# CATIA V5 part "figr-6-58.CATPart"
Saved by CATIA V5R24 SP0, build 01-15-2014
Part number: Part1
Bounding box of the stored display mesh (mm): x -50.648 to 50.648, y -72.183 to 72.183, z -40 to 40
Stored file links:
  D:\KAVITA\CATIA V5-6R2014 Project_ Kavita\CATIA V5-6R2014_partfiles\Partfiles\c06_catia_v5-6r2014_prt\figr-6-58.CATPart
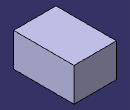
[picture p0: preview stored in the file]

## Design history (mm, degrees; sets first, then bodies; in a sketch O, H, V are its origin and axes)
Body1 (main body)
  Sketch1 on xy-plane, origin (0, 0, 0), H (1, 0, 0), V (0, 1, 0)
    line L1 (-50.6478, 72.1832) -> (50.6478, 72.1832)
    line L2 (50.6478, 72.1832) -> (50.6478, -72.1832)
    line L3 (50.6478, -72.1832) -> (-50.6478, -72.1832)
    line L4 (-50.6478, -72.1832) -> (-50.6478, 72.1832)
    axis line L5 (50.6478, -72.1832) -> (-50.6478, 72.1832)
    horizontal: L1 H, L3 H
    vertical: L2 V, L4 V
    midpoint: O L5
  Pad1: profile Sketch1, direction (0, 0, 1), length 40, mirrored extent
